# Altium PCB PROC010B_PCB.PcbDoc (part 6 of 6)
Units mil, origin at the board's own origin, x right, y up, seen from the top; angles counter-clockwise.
Board outline 3180 x 2565 mil, 6 copper layers (TOP, L2, L3, L4, L5, BOTTOM), stack 55.54 mil thick; 362 components, 264 nets, 1248 pads, 1144 vias.
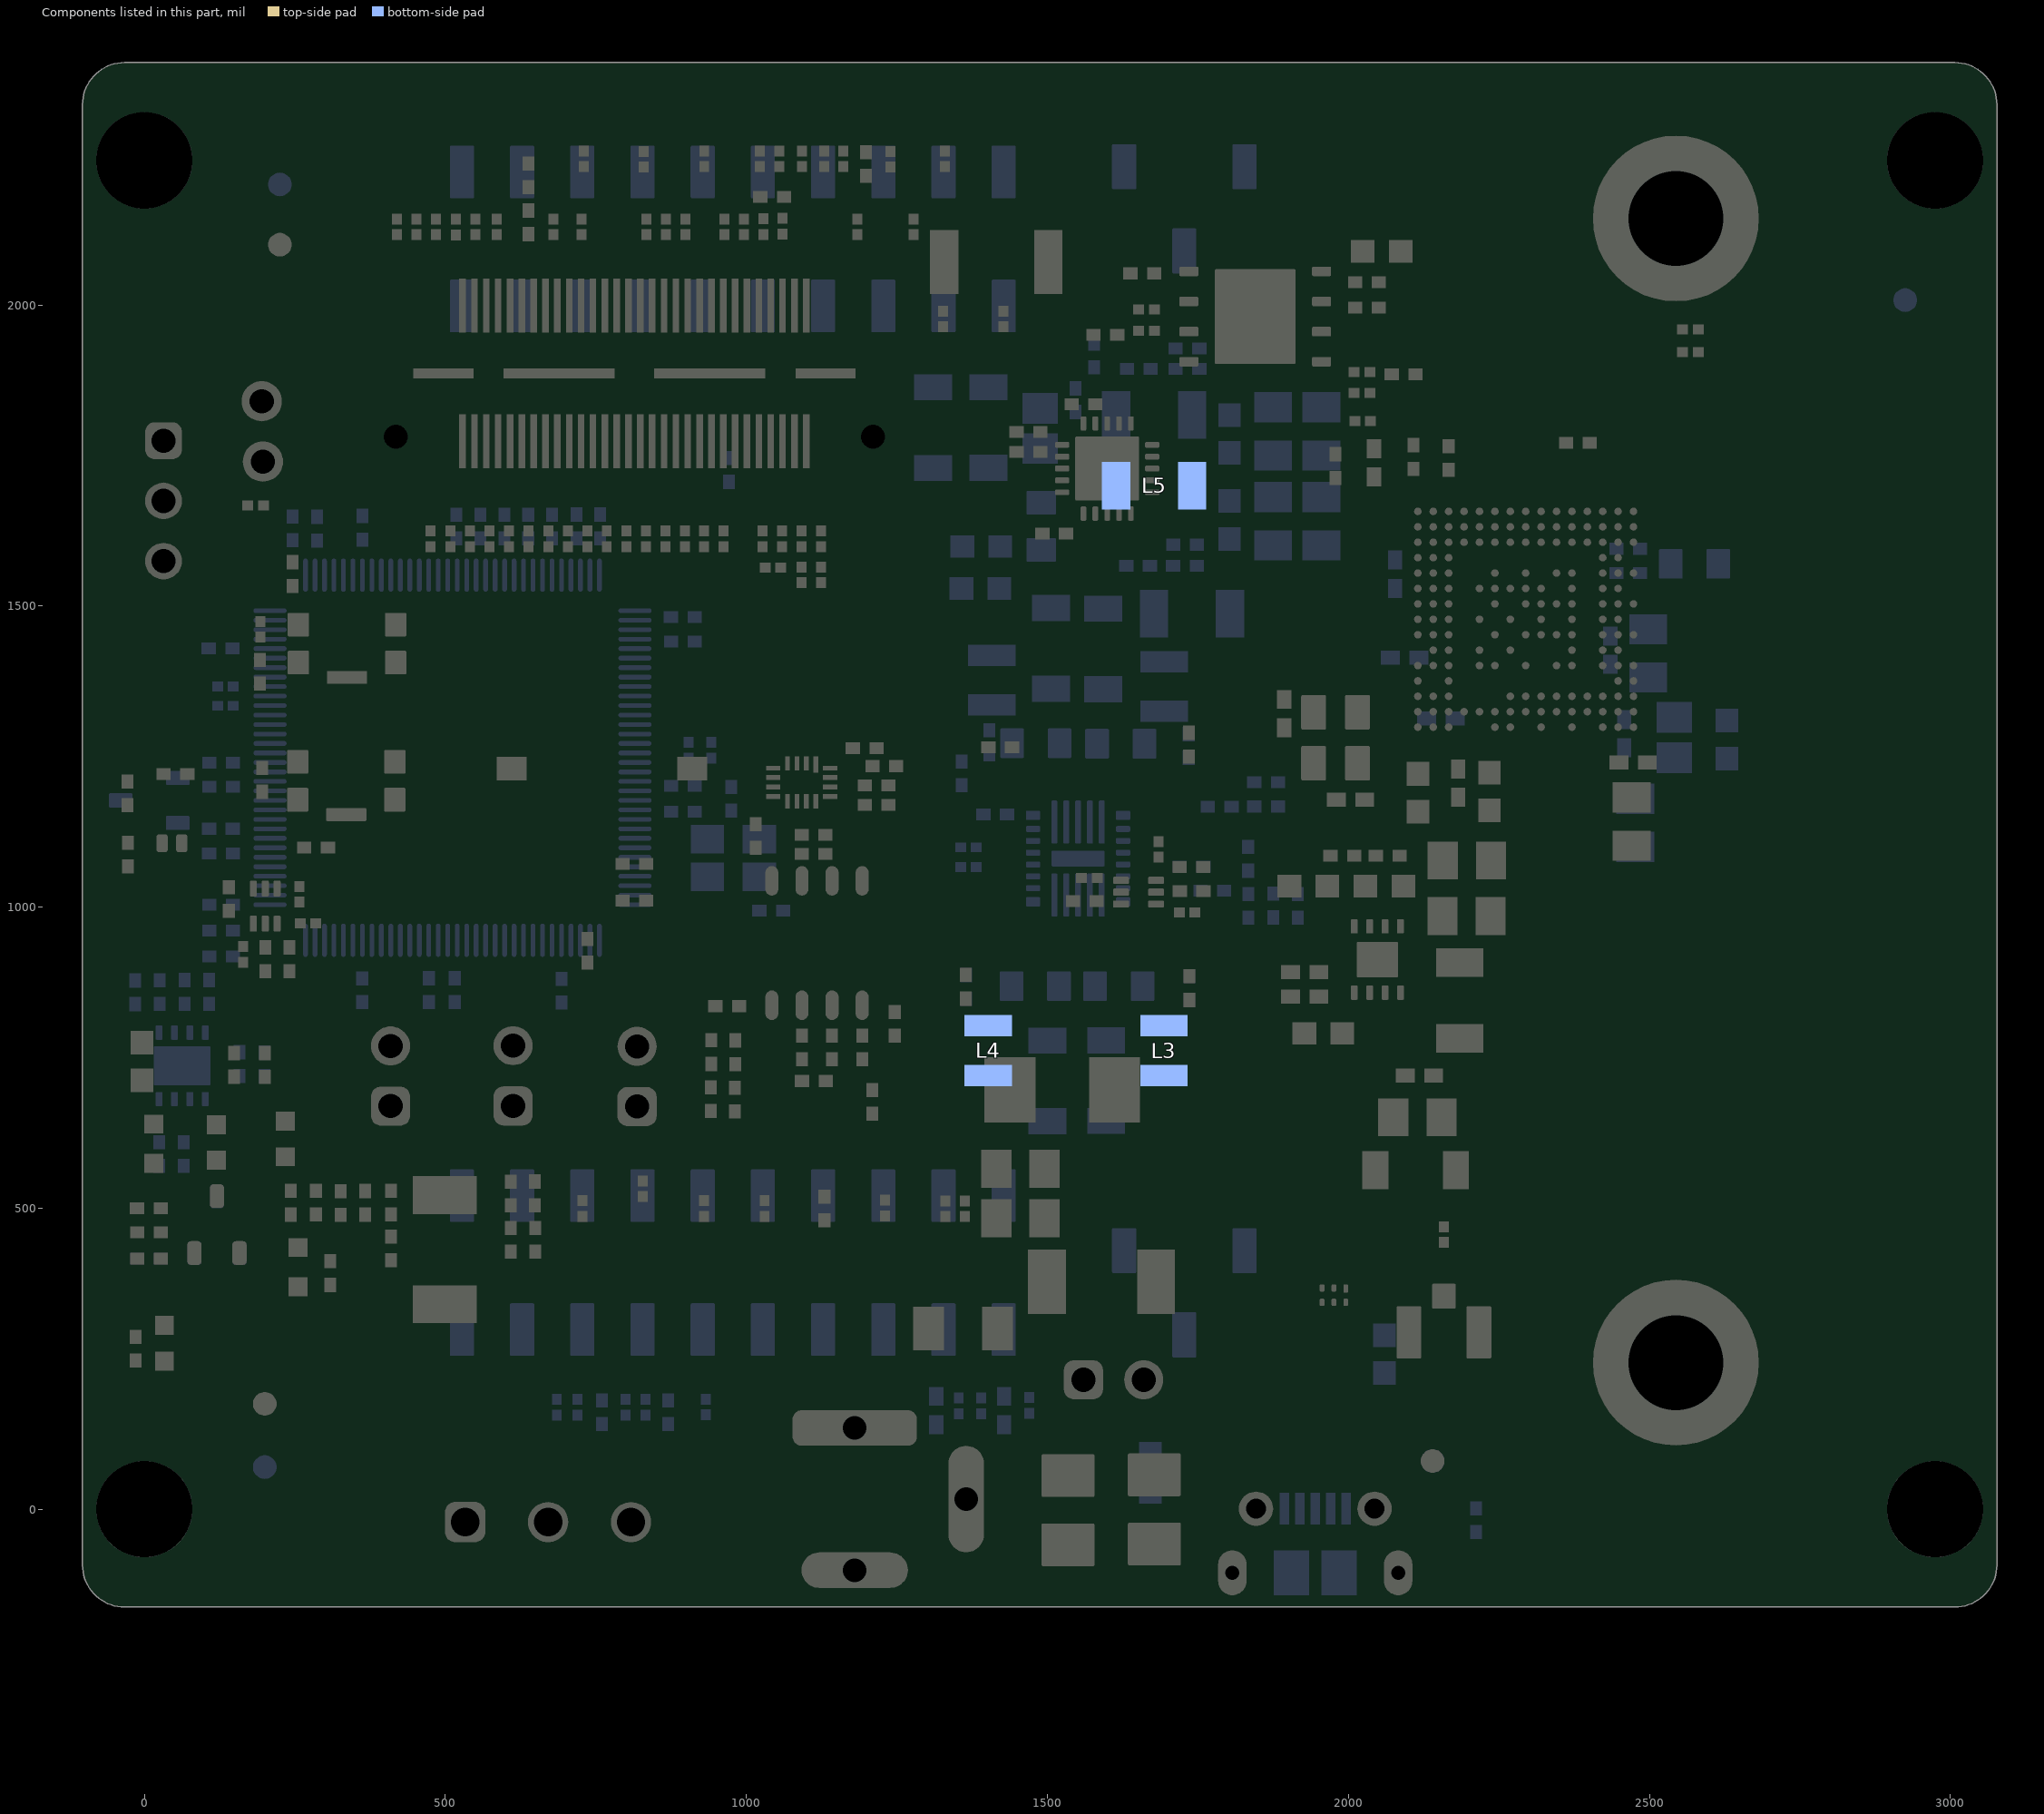
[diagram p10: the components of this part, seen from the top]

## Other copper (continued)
L3:
  pour cut-out: 1600.56,2174.5 1599.22,2181.22 1595.41,2186.91 1589.72,2190.72 1583,2192.06 1576.28,2190.72 1570.59,2186.91 1566.78,2181.22 1565.44,2174.5 1566.78,2167.78 1570.59,2162.09 1576.28,2158.28 1583,2156.94 1589.72,2158.28 1595.41,2162.09 1599.22,2167.78 1600.56,2174.5
  pour cut-out: 1386.56,2172.5 1385.22,2179.22 1381.41,2184.91 1375.72,2188.72 1369,2190.06 1362.28,2188.72 1356.59,2184.91 1352.78,2179.22 1351.44,2172.5 1352.78,2165.78 1356.59,2160.09 1362.28,2156.28 1369,2154.94 1375.72,2156.28 1381.41,2160.09 1385.22,2165.78 1386.56,2172.5
  pour cut-out: 1465.06,1124 1463.72,1130.72 1459.91,1136.41 1454.22,1140.22 1447.5,1141.56 1440.78,1140.22 1435.09,1136.41 1431.28,1130.72 1429.94,1124 1431.28,1117.28 1435.09,1111.59 1440.78,1107.78 1447.5,1106.44 1454.22,1107.78 1459.91,1111.59 1463.72,1117.28 1465.06,1124
  pour cut-out: 1820.56,1102 1819.22,1108.72 1815.41,1114.41 1809.72,1118.22 1803,1119.56 1796.28,1118.22 1790.59,1114.41 1786.78,1108.72 1785.44,1102 1786.78,1095.28 1790.59,1089.59 1796.28,1085.78 1803,1084.44 1809.72,1085.78 1815.41,1089.59 1819.22,1095.28 1820.56,1102
  pour cut-out: 2416.22,1501.7 2414.72,1509.2 2410.48,1515.56 2404.12,1519.8 2396.62,1521.3 2389.12,1519.8 2382.76,1515.56 2378.52,1509.2 2377.02,1501.7 2378.52,1494.2 2382.76,1487.84 2389.12,1483.6 2396.62,1482.1 2404.12,1483.6 2410.48,1487.84 2414.72,1494.2 2416.22,1501.7
  pour cut-out: 2135.56,970.5 2134.22,977.22 2130.41,982.91 2124.72,986.72 2118,988.06 2111.28,986.72 2105.59,982.91 2101.78,977.22 2100.44,970.5 2101.78,963.78 2105.59,958.09 2111.28,954.28 2118,952.94 2124.72,954.28 2130.41,958.09 2134.22,963.78 2135.56,970.5
  pour cut-out: 1881.56,952.5 1880.22,959.22 1876.41,964.91 1870.72,968.72 1864,970.06 1857.28,968.72 1851.59,964.91 1847.78,959.22 1846.44,952.5 1847.78,945.78 1851.59,940.09 1857.28,936.28 1864,934.94 1870.72,936.28 1876.41,940.09 1880.22,945.78 1881.56,952.5
  pour cut-out: 1904.56,1133.5 1903.22,1140.22 1899.41,1145.91 1893.72,1149.72 1887,1151.06 1880.28,1149.72 1874.59,1145.91 1870.78,1140.22 1869.44,1133.5 1870.78,1126.78 1874.59,1121.09 1880.28,1117.28 1887,1115.94 1893.72,1117.28 1899.41,1121.09 1903.22,1126.78 1904.56,1133.5
  pour cut-out: 1933.56,949.5 1932.22,956.22 1928.41,961.91 1922.72,965.72 1916,967.06 1909.28,965.72 1903.59,961.91 1899.78,956.22 1898.44,949.5 1899.78,942.78 1903.59,937.09 1909.28,933.28 1916,931.94 1922.72,933.28 1928.41,937.09 1932.22,942.78 1933.56,949.5
  pour cut-out: 1832.56,689.5 1831.22,696.22 1827.41,701.91 1821.72,705.72 1815,707.06 1808.28,705.72 1802.59,701.91 1798.78,696.22 1797.44,689.5 1798.78,682.78 1802.59,677.09 1808.28,673.28 1815,671.94 1821.72,673.28 1827.41,677.09 1831.22,682.78 1832.56,689.5
  pour cut-out: 1933.56,145.5 1932.22,152.22 1928.41,157.91 1922.72,161.72 1916,163.06 1909.28,161.72 1903.59,157.91 1899.78,152.22 1898.44,145.5 1899.78,138.78 1903.59,133.09 1909.28,129.28 1916,127.94 1922.72,129.28 1928.41,133.09 1932.22,138.78 1933.56,145.5
  pour cut-out: 1041.56,1842.5 1040.22,1849.22 1036.41,1854.91 1030.72,1858.72 1024,1860.06 1017.28,1858.72 1011.59,1854.91 1007.78,1849.22 1006.44,1842.5 1007.78,1835.78 1011.59,1830.09 1017.28,1826.28 1024,1824.94 1030.72,1826.28 1036.41,1830.09 1040.22,1835.78 1041.56,1842.5
  pour cut-out: 807.56,2308.5 806.22,2315.22 802.41,2320.91 796.72,2324.72 790,2326.06 783.28,2324.72 777.59,2320.91 773.78,2315.22 772.44,2308.5 773.78,2301.78 777.59,2296.09 783.28,2292.28 790,2290.94 796.72,2292.28 802.41,2296.09 806.22,2301.78 807.56,2308.5
  pour cut-out: 681.56,850 680.22,856.72 676.41,862.41 670.72,866.22 664,867.56 657.28,866.22 651.59,862.41 647.78,856.72 646.44,850 647.78,843.28 651.59,837.59 657.28,833.78 664,832.44 670.72,833.78 676.41,837.59 680.22,843.28 681.56,850
  pour cut-out: 741.56,125.5 740.22,132.22 736.41,137.91 730.72,141.72 724,143.06 717.28,141.72 711.59,137.91 707.78,132.22 706.44,125.5 707.78,118.78 711.59,113.09 717.28,109.28 724,107.94 730.72,109.28 736.41,113.09 740.22,118.78 741.56,125.5
  pour cut-out: 825.56,128.5 824.22,135.22 820.41,140.91 814.72,144.72 808,146.06 801.28,144.72 795.59,140.91 791.78,135.22 790.44,128.5 791.78,121.78 795.59,116.09 801.28,112.28 808,110.94 814.72,112.28 820.41,116.09 824.22,121.78 825.56,128.5
  pour cut-out: 467.56,2168.5 466.22,2175.22 462.41,2180.91 456.72,2184.72 450,2186.06 443.28,2184.72 437.59,2180.91 433.78,2175.22 432.44,2168.5 433.78,2161.78 437.59,2156.09 443.28,2152.28 450,2150.94 456.72,2152.28 462.41,2156.09 466.22,2161.78 467.56,2168.5
  pour cut-out: 479.56,1272.5 478.22,1279.22 474.41,1284.91 468.72,1288.72 462,1290.06 455.28,1288.72 449.59,1284.91 445.78,1279.22 444.44,1272.5 445.78,1265.78 449.59,1260.09 455.28,1256.28 462,1254.94 468.72,1256.28 474.41,1260.09 478.22,1265.78 479.56,1272.5
  pour cut-out: 468.56,280.5 467.22,287.22 463.41,292.91 457.72,296.72 451,298.06 444.28,296.72 438.59,292.91 434.78,287.22 433.44,280.5 434.78,273.78 438.59,268.09 444.28,264.28 451,262.94 457.72,264.28 463.41,268.09 467.22,273.78 468.56,280.5
  pour cut-out: 579.56,219.5 578.22,226.22 574.41,231.91 568.72,235.72 562,237.06 555.28,235.72 549.59,231.91 545.78,226.22 544.44,219.5 545.78,212.78 549.59,207.09 555.28,203.28 562,201.94 568.72,203.28 574.41,207.09 578.22,212.78 579.56,219.5
  pour cut-out: 527.56,221.5 526.22,228.22 522.41,233.91 516.72,237.72 510,239.06 503.28,237.72 497.59,233.91 493.78,228.22 492.44,221.5 493.78,214.78 497.59,209.09 503.28,205.28 510,203.94 516.72,205.28 522.41,209.09 526.22,214.78 527.56,221.5
  pour cut-out: 491.56,241.5 490.22,248.22 486.41,253.91 480.72,257.72 474,259.06 467.28,257.72 461.59,253.91 457.78,248.22 456.44,241.5 457.78,234.78 461.59,229.09 467.28,225.28 474,223.94 480.72,225.28 486.41,229.09 490.22,234.78 491.56,241.5
  pour cut-out: 366.56,1818.5 365.22,1825.22 361.41,1830.91 355.72,1834.72 349,1836.06 342.28,1834.72 336.59,1830.91 332.78,1825.22 331.44,1818.5 332.78,1811.78 336.59,1806.09 342.28,1802.28 349,1800.94 355.72,1802.28 361.41,1806.09 365.22,1811.78 366.56,1818.5
  pour cut-out: 332.56,1776.5 331.22,1783.22 327.41,1788.91 321.72,1792.72 315,1794.06 308.28,1792.72 302.59,1788.91 298.78,1783.22 297.44,1776.5 298.78,1769.78 302.59,1764.09 308.28,1760.28 315,1758.94 321.72,1760.28 327.41,1764.09 331.22,1769.78 332.56,1776.5
  pour cut-out: 284.56,1680.5 283.22,1687.22 279.41,1692.91 273.72,1696.72 267,1698.06 260.28,1696.72 254.59,1692.91 250.78,1687.22 249.44,1680.5 250.78,1673.78 254.59,1668.09 260.28,1664.28 267,1662.94 273.72,1664.28 279.41,1668.09 283.22,1673.78 284.56,1680.5
  pour cut-out: 142.56,686.5 141.22,693.22 137.41,698.91 131.72,702.72 125,704.06 118.28,702.72 112.59,698.91 108.78,693.22 107.44,686.5 108.78,679.78 112.59,674.09 118.28,670.28 125,668.94 131.72,670.28 137.41,674.09 141.22,679.78 142.56,686.5
  pour cut-out: 231.56,489.5 230.22,496.22 226.41,501.91 220.72,505.72 214,507.06 207.28,505.72 201.59,501.91 197.78,496.22 196.44,489.5 197.78,482.78 201.59,477.09 207.28,473.28 214,471.94 220.72,473.28 226.41,477.09 230.22,482.78 231.56,489.5
  pour cut-out: 334.56,451.5 333.22,458.22 329.41,463.91 323.72,467.72 317,469.06 310.28,467.72 304.59,463.91 300.78,458.22 299.44,451.5 300.78,444.78 304.59,439.09 310.28,435.28 317,433.94 323.72,435.28 329.41,439.09 333.22,444.78 334.56,451.5
  pour cut-out: 72.56,973.5 71.22,980.22 67.41,985.91 61.72,989.72 55,991.06 48.28,989.72 42.59,985.91 38.78,980.22 37.44,973.5 38.78,966.78 42.59,961.09 48.28,957.28 55,955.94 61.72,957.28 67.41,961.09 71.22,966.78 72.56,973.5
  pour cut-out: -14.44,807.5 -15.78,814.22 -19.59,819.91 -25.28,823.72 -32,825.06 -38.72,823.72 -44.41,819.91 -48.22,814.22 -49.56,807.5 -48.22,800.78 -44.41,795.09 -38.72,791.28 -32,789.94 -25.28,791.28 -19.59,795.09 -15.78,800.78 -14.44,807.5
  pour cut-out: 80.56,906.5 79.22,913.22 75.41,918.91 69.72,922.72 63,924.06 56.28,922.72 50.59,918.91 46.78,913.22 45.44,906.5 46.78,899.78 50.59,894.09 56.28,890.28 63,888.94 69.72,890.28 75.41,894.09 79.22,899.78 80.56,906.5
  pour cut-out: -30.44,715.5 -31.78,722.22 -35.59,727.91 -41.28,731.72 -48,733.06 -54.72,731.72 -60.41,727.91 -64.22,722.22 -65.56,715.5 -64.22,708.78 -60.41,703.09 -54.72,699.28 -48,697.94 -41.28,699.28 -35.59,703.09 -31.78,708.78 -30.44,715.5
  pour cut-out: 6.44,373.5 5.1,380.22 1.3,385.91 -4.4,389.72 -11.12,391.06 -17.84,389.72 -23.54,385.91 -27.34,380.22 -28.68,373.5 -27.34,366.78 -23.54,361.09 -17.84,357.28 -11.12,355.94 -4.4,357.28 1.3,361.09 5.1,366.78 6.44,373.5
  pour cut-out: 6.23,531.5 4.89,538.22 1.09,543.91 -4.61,547.72 -11.33,549.06 -18.05,547.72 -23.74,543.91 -27.55,538.22 -28.89,531.5 -27.55,524.78 -23.74,519.09 -18.05,515.28 -11.33,513.94 -4.61,515.28 1.09,519.09 4.89,524.78 6.23,531.5
  pour cut-out: 1425.56,1065 1424.22,1071.72 1420.41,1077.41 1414.72,1081.22 1408,1082.56 1401.28,1081.22 1395.59,1077.41 1391.78,1071.72 1390.44,1065 1391.78,1058.28 1395.59,1052.59 1401.28,1048.78 1408,1047.44 1414.72,1048.78 1420.41,1052.59 1424.22,1058.28 1425.56,1065
  pour cut-out: 1380.56,918 1379.22,924.72 1375.41,930.41 1369.72,934.22 1363,935.56 1356.28,934.22 1350.59,930.41 1346.78,924.72 1345.44,918 1346.78,911.28 1350.59,905.59 1356.28,901.78 1363,900.44 1369.72,901.78 1375.41,905.59 1379.22,911.28 1380.56,918
  pour cut-out: 1161.56,2065.5 1160.22,2072.22 1156.41,2077.91 1150.72,2081.72 1144,2083.06 1137.28,2081.72 1131.59,2077.91 1127.78,2072.22 1126.44,2065.5 1127.78,2058.78 1131.59,2053.09 1137.28,2049.28 1144,2047.94 1150.72,2049.28 1156.41,2053.09 1160.22,2058.78 1161.56,2065.5
  pour cut-out: 1225.56,2281.5 1224.22,2288.22 1220.41,2293.91 1214.72,2297.72 1208,2299.06 1201.28,2297.72 1195.59,2293.91 1191.78,2288.22 1190.44,2281.5 1191.78,2274.78 1195.59,2269.09 1201.28,2265.28 1208,2263.94 1214.72,2265.28 1220.41,2269.09 1224.22,2274.78 1225.56,2281.5
  pour cut-out: 596.76,532.5 595.42,539.22 591.61,544.91 585.92,548.72 579.2,550.06 572.48,548.72 566.78,544.91 562.98,539.22 561.64,532.5 562.98,525.78 566.78,520.09 572.48,516.28 579.2,514.94 585.92,516.28 591.61,520.09 595.42,525.78 596.76,532.5
  pour cut-out: 1589.58,2229.48 1588.24,2236.2 1584.43,2241.9 1578.74,2245.7 1572.02,2247.04 1565.3,2245.7 1559.61,2241.9 1555.8,2236.2 1554.46,2229.48 1555.8,2222.76 1559.61,2217.06 1565.3,2213.26 1572.02,2211.92 1578.74,2213.26 1584.43,2217.06 1588.24,2222.76 1589.58,2229.48
  pour cut-out: 1604.43,2016.01 1603.09,2022.73 1599.28,2028.42 1593.59,2032.23 1586.87,2033.57 1580.15,2032.23 1574.45,2028.42 1570.65,2022.73 1569.31,2016.01 1570.65,2009.29 1574.45,2003.59 1580.15,1999.79 1586.87,1998.45 1593.59,1999.79 1599.28,2003.59 1603.09,2009.29 1604.43,2016.01
  pour cut-out: 2001.15,1420.93 2001.15,1399.1 2010.71,1389.54 2033.02,1389.54 2042.9,1399.42 2042.9,1422.35 2034.76,1430.49 2010.7,1430.49
  pour cut-out: 2388.47,801.94 2388.47,787.64 2399.47,776.64 2411.42,776.64 2420.44,785.66 2420.44,800.04 2411.42,809.06 2395.59,809.06
  pour cut-out: 2325.12,882.28 2325.12,867.98 2336.12,856.98 2348.06,856.98 2357.09,866 2357.09,880.38 2348.06,889.4 2332.24,889.4
  pour cut-out: 2072.08,1321.15 2072.08,1305.01 2081.98,1295.11 2101.41,1295.11 2114.7,1308.4 2114.7,1320.49 2104.79,1330.41 2081.34,1330.41
  pour cut-out: 1755.04,2103.69 1755.04,2078.14 1763.26,2069.92 1780.02,2069.92 1796.11,2086.02 1796.11,2105.18 1789.22,2112.08 1763.42,2112.08
  pour cut-out: 2060.04,2009.43 2060.04,1983.88 2068.26,1975.66 2085.02,1975.66 2101.11,1991.76 2101.11,2010.92 2094.22,2017.82 2068.42,2017.82
  pour cut-out: 2221.47,724.94 2221.47,706.23 2231.08,696.62 2245.63,696.62 2253.44,704.43 2253.44,724.46 2245.84,732.06 2228.59,732.06
  pour cut-out: 216.76,785.5 215.42,792.22 211.62,797.91 205.92,801.72 199.2,803.06 192.48,801.72 186.79,797.91 182.98,792.22 181.64,785.5 182.98,778.78 186.79,773.09 192.48,769.28 199.2,767.94 205.92,769.28 211.62,773.09 215.42,778.78 216.76,785.5
  pour cut-out: 1078.54,924.46 1077.21,931.18 1073.4,936.88 1067.7,940.68 1060.98,942.02 1054.27,940.68 1048.57,936.88 1044.76,931.18 1043.43,924.46 1044.76,917.74 1048.57,912.05 1054.27,908.24 1060.98,906.9 1067.7,908.24 1073.4,912.05 1077.21,917.74 1078.54,924.46
  pour cut-out: 2470.18,1676.36 2470.18,1662.36 2496.03,1636.52 2510.94,1636.52 2510.94,1707.84 2501.66,1707.84
  pour cut-out: 930.41,1685.77 930.41,1690.52 920.25,1700.69 920.25,1723.05 929.65,1732.45 971.87,1732.45 974.54,1729.79
  pour cut-out: 2186.37,1031.38 2185.03,1038.1 2181.23,1043.8 2175.53,1047.6 2168.81,1048.94 2162.09,1047.6 2156.4,1043.8 2152.59,1038.1 2151.26,1031.38 2152.59,1024.67 2156.4,1018.97 2162.09,1015.16 2168.81,1013.83 2175.53,1015.16 2181.23,1018.97 2185.03,1024.67 2186.37,1031.38
  pour cut-out: 2269.24,957 2269.24,942.7 2280.24,931.7 2292.18,931.7 2301.2,940.73 2301.2,955.1 2292.18,964.12 2276.36,964.12
  text "3" at 68.06,102.36 h50
  text ".Layer_Name" at -523,-1458.49 h60
L4:
  drawing of 93 lines, arcs and shapes, not listed
  text "4" at 68.06,102.36 h50
  text ".Layer_Name" at -523,-1458.49 h60
L5:
  text "5" at 68.06,102.36 h50
  text ".Layer_Name" at -523,-1458.49 h60
BOTTOM:
  pour cut-out: 2691.21,2143.55 2689.4,2166.59 2684.01,2189.06 2675.16,2210.41 2663.09,2230.11 2648.08,2247.68 2630.51,2262.69 2610.81,2274.76 2589.46,2283.61 2566.99,2289 2543.95,2290.81 2520.91,2289 2498.44,2283.61 2477.09,2274.76 2457.39,2262.69 2439.82,2247.68 2424.81,2230.11 2412.74,2210.41 2403.89,2189.06 2398.5,2166.59 2396.69,2143.55 2398.5,2120.51 2403.89,2098.04 2412.74,2076.69 2424.81,2056.99 2439.82,2039.42 2457.39,2024.41 2477.09,2012.34 2498.44,2003.49 2520.91,1998.1 2543.95,1996.29 2566.99,1998.1 2589.46,2003.49 2610.81,2012.34 2630.51,2024.41 2648.08,2039.42 2663.09,2056.99 2675.16,2076.69 2684.01,2098.04 2689.4,2120.51 2691.21,2143.55
  pour cut-out: 2691.21,243.55 2689.4,266.59 2684.01,289.06 2675.16,310.41 2663.09,330.11 2648.08,347.68 2630.51,362.69 2610.81,374.76 2589.46,383.61 2566.99,389 2543.95,390.81 2520.91,389 2498.44,383.61 2477.09,374.76 2457.39,362.69 2439.82,347.68 2424.81,330.11 2412.74,310.41 2403.89,289.06 2398.5,266.59 2396.69,243.55 2398.5,220.51 2403.89,198.04 2412.74,176.69 2424.81,156.99 2439.82,139.42 2457.39,124.41 2477.09,112.34 2498.44,103.49 2520.91,98.1 2543.95,96.29 2566.99,98.1 2589.46,103.49 2610.81,112.34 2630.51,124.41 2648.08,139.42 2663.09,156.99 2675.16,176.69 2684.01,198.04 2689.4,220.51 2691.21,243.55
  pour cut-out: 2027.6,469.16 2026.1,476.66 2021.86,483.02 2015.5,487.26 2008,488.76 2000.5,487.26 1994.14,483.02 1989.9,476.66 1988.4,469.16 1989.9,461.66 1994.14,455.3 2000.5,451.06 2008,449.56 2015.5,451.06 2021.86,455.3 2026.1,461.66 2027.6,469.16
  pour cut-out: 2559.6,1753.5 2558.1,1761 2553.86,1767.36 2547.5,1771.6 2540,1773.1 2532.5,1771.6 2526.14,1767.36 2521.9,1761 2520.4,1753.5 2521.9,1746 2526.14,1739.64 2532.5,1735.4 2540,1733.9 2547.5,1735.4 2553.86,1739.64 2558.1,1746 2559.6,1753.5
  pour cut-out: 2597.6,1841.5 2596.1,1849 2591.86,1855.36 2585.5,1859.6 2578,1861.1 2570.5,1859.6 2564.14,1855.36 2559.9,1849 2558.4,1841.5 2559.9,1834 2564.14,1827.64 2570.5,1823.4 2578,1821.9 2585.5,1823.4 2591.86,1827.64 2596.1,1834 2597.6,1841.5
  pour cut-out: 2920.17,1934.93 2918.67,1942.43 2914.43,1948.79 2908.07,1953.03 2900.57,1954.53 2893.07,1953.03 2886.71,1948.79 2882.47,1942.43 2880.97,1934.93 2882.47,1927.43 2886.71,1921.07 2893.07,1916.83 2900.57,1915.33 2908.07,1916.83 2914.43,1921.07 2918.67,1927.43 2920.17,1934.93
  pour cut-out: 2863.6,1991.5 2862.1,1999 2857.86,2005.36 2851.5,2009.6 2844,2011.1 2836.5,2009.6 2830.14,2005.36 2825.9,1999 2824.4,1991.5 2825.9,1984 2830.14,1977.64 2836.5,1973.4 2844,1971.9 2851.5,1973.4 2857.86,1977.64 2862.1,1984 2863.6,1991.5
  pour cut-out: 2151.7,1291.49 2147.75,1291.49 2115.09,1258.83 2115.09,1267.92 2129.83,1282.66 2129.83,1293.11 2123.32,1299.62 2097.57,1299.62 2093.78,1295.83 2084.86,1295.83 2077.28,1303.41 2077.28,1358.83 2083.95,1365.49 2097.57,1365.49 2103.93,1359.14 2103.93,1333.24 2107.42,1329.76 2150.88,1329.76 2156.72,1323.91 2156.72,1296.51
  pour cut-out: 2115.09,1148.14 2115.09,1128.65 2129.49,1114.24 2123.74,1108.49 2093.29,1108.49 2085.17,1116.61 2085.17,1128.76 2096.68,1140.27 2107.22,1140.27
  text "6" at 101.39,102.36 h50
  text ".Layer_Name" at -523,-1458.49 h60

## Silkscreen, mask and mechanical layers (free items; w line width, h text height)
Top Overlay:
  circle w6: c894.62,627.38 r17.83
  circle w6: c485.18,628.05 r17.83
  circle w6: c688.62,628.38 r17.83
  circle w6: c-42.06,1837.57 r14.11
  circle w6: c1489.33,267.42 r14.11
  circle w6: c2007.63,386.64 r7.14
  text "HD_CONN" at 325,1793.5 h35 r90
  text "GND" at -48.33,1613 h35 r90
  text "1243/1443-EVM" at 648,1502.5 h30
  text "PROC010 REV B" at 652,1437.33 h30
  text "GPIO1" at 504.55,1382.74 h35 r90
  text "SPI" at 569.09,1196.05 h35 r90
  text "CAN" at 987.03,1180.35 h35 r90
  text "NRST" at 504.55,1144.97 h35 r90
  text "ON" at 914.7,1109.62 h35 r90.31
  text "SOP2" at 424,836.5 h35 r90
  text "SOP1" at 624,831.5 h35 r90
  text "SOP0" at 829,831.5 h35 r90
  text "5V" at 278.28,691.14 h35 r90
  text "NERR_OUT" at 107.44,686.5 h35 r90
  text "5V_IN" at 1117.5,271 h35
  text "NRST" at 298.71,228.51 h35 r90
  text "WARMRST" at 134.9,184 h32 r89.47
  text "GND" at 679.67,133 h35 r90
  text "CAN_L" at 963.67,65 h35 r90
  text "CAN_H" at 439.67,64 h35 r90
  text "USB" at 1958,-52.5 h35 r90
  text ".Layer_Name" at -523,-1458.49 h60
Bottom Overlay:
  drawing of 8192 lines, arcs and shapes, not listed
  text "GND" at 1635.34,2394.5 h35 r90
  text "GND" at 1736.34,2394.5 h35 r90
  text "GND" at 544.67,2389.5 h35 r90
  text "3V3" at 1842.66,2383.93 h30 r90
  text "GND" at 691.34,695.5 h35 r90
  text "GND" at 1639.34,609.5 h35 r90
  text "GND" at 1748.34,608.5 h35 r90
  text ".Layer_Name" at -523,-1458.49 h60
Top Paste:
  text ".Layer_Name" at -523,-1458.49 h60
Bottom Paste:
  text ".Layer_Name" at -523,-1458.49 h60
Top Solder:
  text ".Layer_Name" at -523,-1458.49 h60
  text ".Layer_Name" at -523,-1458.49 h60
Bottom Solder:
  pour cut-out: 1481.31,1176.95 1481.31,1160.02 1464.38,1160.02 1464.38,1144.28 1495.09,1144.28 1495.09,1176.95 1481.31,1176.95
  pour cut-out: 1620.69,1176.95 1620.69,1160.02 1637.62,1160.02 1637.62,1144.28 1606.91,1144.28 1606.91,1176.95 1620.69,1176.95
  pour cut-out: 1481.31,984.05 1481.31,1000.98 1464.38,1000.98 1464.38,1016.72 1495.09,1016.72 1495.09,984.05 1481.31,984.05
  pour cut-out: 1620.69,984.05 1620.69,1000.98 1637.62,1000.98 1637.62,1016.72 1606.91,1016.72 1606.91,984.05 1620.69,984.05
  text ".Layer_Name" at -523,-1458.49 h60
Drill Guide:
  text ".Layer_Name" at -523,-1458.49 h60
M1 Board Outline:
  the board outline again, w10
M3 3D STEP Top:
  drawing of 2189 lines, arcs and shapes, not listed
  text ".Layer_Name" at -523,-1458.49 h60
M4 3D STEP Bottom:
  drawing of 3548 lines, arcs and shapes, not listed
  text ".Layer_Name" at -523,-1458.49 h60
M5 Assembly Top:
  region: 1573.73,232.01 1541.58,232.01 1541.58,199 1573.73,199
  rectangle: 3.25,1755.12 61.5,1795.24
  rectangle: 392.36,652.17 425.79,686.46
  rectangle: 595.1,653.88 628.11,683.89
  rectangle: 804.71,651.74 836.86,684.75
  rectangle: 505.35,-45.85 561.85,-0.8
  lines w10: -1392,-1530.17 5208,-1530.17 ; -1392,-1326.83 5210,-1326.83 ; -1392,-1123.5 -1392,-1733.5 2613,-1733.5 5210,-1733.5 5210,-1123.5 -1391.5,-1123.5 -1391.5,-1733.5 184,-1733.5 ; 1073,-1733.5 1073,-1123.5 ; 2340,-1326.83 2340,-1123.5 ; 3180,-1326.83 3180,-1123.5 ; 3802,-1740 3802,-1537.17
  text "COMPONENTS MARKED 'DNP' SHOULD NOT BE POPULATED." at 53.5,-918.5 h60
  text "ASSEMBLY VARIANT:" at 53,-1034 h60
  text ".VariantName" at 1089,-1034 h60
  text "PCB VIEWED FROM TOP SIDE" at -1328.5,-1255.67 h60
  text "BOARD #:" at 1148,-1255.67 h60
  text ".PRJ_Number" at 1693.5,-1255.67 h60
  text "REV:" at 2538,-1255.67 h60
  text ".PCB_Rev" at 2829.5,-1255.67 h60
  text "SVN REV:" at 3376,-1255.67 h60
  text ".VersionControl_RevNumber" at 3882,-1255.67 h60
  text "TID #:" at 1148,-1459 h60
  text ".TID" at 1693.5,-1459 h60
  text "PLOT NAME =" at -1328.5,-1664.34 h60
  text ".plot_File_Name" at -523,-1664.34 h60
  text "GENERATED    :" at 1150,-1664.34 h60
  text ".Print_Date" at 2019.5,-1664.34 h60
  text ".Print_Time" at 2748.5,-1664.34 h60
  text "TEXAS INSTRUMENTS" at 4013,-1664.34 h60
M6 Assembly Bottom:
  rectangle: 477.5,309.5 520.87,346.52
  rectangle: 477.5,2009.5 520.08,2041.65
  lines w10: -1392.5,-1327.33 5209.5,-1327.33 ; -1390.5,-1530.67 5209.5,-1530.67 ; 15.5,-1740.5 15.5,-1537.67 ; 637.5,-1327.33 637.5,-1124 ; 1477.5,-1327.33 1477.5,-1124 ; 2744.5,-1734 2744.5,-1124 ; 3633.5,-1734 5209,-1734 5209,-1124 -1392.5,-1124 -1392.5,-1734 1204.5,-1734 5209.5,-1734 5209.5,-1124
  text "COMPONENTS MARKED 'DNP' SHOULD NOT BE POPULATED." at 5002,-918 h60
  text ".VariantName" at 3958,-1034 h60
  text "ASSEMBLY VARIANT:" at 4997,-1034 h60
  text ".VersionControl_RevNumber" at -64.5,-1256.17 h60
  text "SVN REV:" at 441.5,-1256.17 h60
  text ".PCB_Rev" at 988,-1256.17 h60
  text "REV:" at 1279.5,-1256.17 h60
  text ".PRJ_Number" at 2124,-1256.17 h60
  text "BOARD #:" at 2669.5,-1256.17 h60
  text "PCB VIEWED FROM BOTTOM SIDE" at 5146,-1256.17 h60
  text ".TID" at 2124,-1459.5 h60
  text "TID #:" at 2669.5,-1459.5 h60
  text "TEXAS INSTRUMENTS" at -195.5,-1664.84 h60
  text ".Print_Time" at 1069,-1664.84 h60
  text ".Print_Date" at 1798,-1664.84 h60
  text "GENERATED    :" at 2667.5,-1664.84 h60
  text ".plot_File_Name" at 4340.5,-1664.84 h60
  text "PLOT NAME =" at 5146,-1664.84 h60
1:
  lines w1: 2633.36,918.75 2633.36,1666.78 3042.41,1666.78 3042.41,918.75 2633.36,918.75
2:
  drawing of 7 lines, arcs and shapes, not listed
M9 Title Sheet:
  drawing of 59 lines, arcs and shapes, not listed
  text "1" at -360.16,7436.5 h70
  text "2" at 2135.5,7436.5 h70
  text "3" at 4624.84,7436.5 h70
  text "4" at 7131.51,7436.5 h70
  text "5" at 9630.5,7436.5 h70
  text "6" at 12135.5,7436.5 h70
  text "A" at -1516.5,6293.5 h70
  text "A" at 13283.5,6293.5 h70
  text "B" at -1516.5,3913.5 h70
  text "B" at 13283.5,3913.5 h70
  text "C" at -1516.5,1538.5 h70
  text "C" at 13283.5,1538.5 h70
  text "PROJECT TITLE:" at 10243.5,-322.5 h45
  text ".PRJ_Title" at 10293.5,-455.83 h70
  text "DESIGNED FOR:" at 10243.5,-623.5 h45
  text ".PRJ_Customer" at 10293.5,-763.5 h70
  text "D" at -1516.5,-831.5 h70
  text "D" at 13283.5,-831.5 h70
  text "FILE NAME:" at 10243.5,-923.5 h45
  text ".PCB_File_Name_No_Path" at 10293.5,-1043.5 h70
  text "Texas Instruments (TI) and/or its licensors do not warrant the accuracy or completeness of this specification" at 5274,-1205.34 h45
  text "ENGINEER:" at 10243.5,-1213.5 h45
  text "LAYOUT BY:" at 11748.5,-1213.5 h45
  text "or any information contained therein. TI and/or its licensors do not warrant that this design will meet" at 5229.01,-1318 h45
  text ".PRJ_Engineer" at 10293.5,-1368.49 h70
  text ".PCB_Layout" at 11799,-1368.49 h70
  text "the specifications, will be suitable for your application or fit for any particular purpose, or will operate in" at 5229.01,-1430.67 h45
  text "ALTIUM DESIGNER VERSION:" at 11748.5,-1523.5 h45
  text "an implementation. TI and/or its licensors do not warrant that the design is production worthy. You should" at 5229.01,-1543.33 h45
  text "completely validate and test your design implementation to confirm the system functionality for your application." at 5274,-1656 h45
  text ".print_Scale" at 10293.5,-1656.83 h70
  text ".Application_BuildNumber" at 11799,-1656.83 h70
  text "1" at -360.16,-1863.5 h70
  text "2" at 2135.5,-1863.5 h70
  text "3" at 4624.84,-1863.5 h70
  text "4" at 7131.51,-1863.5 h70
  text "5" at 9630.5,-1863.5 h70
  text "WO # : 307314-7312-D" at 12135.5,-1863.5 h70
M10 Fab Notes:
  drawing of 211 lines, arcs and shapes, not listed
  text "DESIGN INFORMATION" at 11282.02,5756.17 h60
  text "3.9" at 11684.18,5628.43 h60
  text "MIN. TRACK WIDTH:" at 10637.46,5624.05 h60
  text "MIL" at 11888.46,5624.05 h60
  text "3.9" at 11684.18,5505.31 h60
  text "MIN. CLEARANCE:" at 10637.46,5499.92 h60
  text "MIL" at 11887.46,5493.05 h60
  text "13.77" at 11607.21,5377.48 h60
  text "MIN. VIA PAD SIZE:" at 10637.46,5375.8 h60
  text "MIL" at 11888.46,5375.8 h60
  text "0.05mm (2MIL)" at 11332.46,5245.9 h60
  text "MINIMUM ANNULAR RING" at 10308.23,5237.67 h60
  text "EXTERNAL" at 12040.46,5237.67 h60
  text "PER" at 10508.23,5127.55 h60
  text "IPC-D-275 CLASS 2 LEVEL C" at 10728.23,5127.54 h60
  text "MIL, HOLES" at 12216.46,5027.07 h60
  text "+/-" at 11824,5018.48 h60
  text "+/-" at 12678,5018.48 h60
  text "REGISTRATION TOLERANCES:" at 10308.23,5017.42 h60
  text "METAL" at 11508,5017.42 h60
  text "2" at 12084.2,5017.42 h60
  text "3" at 12917.2,5017.42 h60
  text "MIL" at 13033.46,5017.42 h60
  text "HOLE SIZE TOLERANCE (UNLESS OTHERWISE SPECIFIED):" at 10308.23,4919.1 h60
  text "+/-" at 12678,4916.23 h60
  text "3" at 12917.2,4915.17 h60
  text "MIL" at 13033.46,4915.17 h60
  text "MATERIAL:" at 10233.46,4777.52 h60
  text "FR-4 High Tg" at 11219.9,4649 h60
  text "REFER STACKUP" at 12479.29,4645.02 h60
  text "X" at 11955.46,4641.01 h60
  text "FR-408" at 10654.46,4636.49 h60
  text "OTHER" at 12142.46,4636.49 h60
  text "X" at 12138.91,4493.91 h60
  text "62 MIL (1.6mm) +/-10%" at 10974.56,4493.46 h60
  text "57.14 MIL +/-10%" at 12537.59,4492.07 h50
  text "THICKNESS:" at 10308.23,4485.24 h60
  text "OTHER" at 12259.46,4485.24 h60
  text "TOLERANCE:" at 10308.23,4346.92 h60
  text "X" at 11156.46,4346.92 h60
  text "ANSI IPC-6012 TYPE 3 CLASS 2" at 11334.48,4346.92 h60
  text "OTHER +/-" at 11334.46,4202.73 h60
  text "BOW & TWIST:" at 10308.23,4057.54 h60
  text "X" at 11156.46,4057.54 h60
  text "ANSI IPC-6012 TYPE 3 CLASS 2" at 11334.48,4057.54 h60
  text "OTHER +/-" at 11334.46,3910.85 h60
  text "DRILLING:" at 10233.46,3780.23 h60
  text "NC_DRILL FILES" at 11994.46,3675.04 h60
  text "REFERENCE:" at 10308.23,3671.1 h60
  text "X" at 10965.46,3671.01 h60
  text "AS SHOWN" at 11143.46,3671.1 h60
  text "X" at 11866.46,3671.1 h60
  text "OTHER" at 12292.46,3528.85 h60
  text "PTH COPPER THICKNESS:" at 10307.91,3525.32 h60
  text "X" at 11447.14,3525.32 h60
  text "20-30 um" at 11575.14,3525.32 h60
  text "BOARD FINISH:" at 10233.46,3377.73 h60
  text "SILKSCREEN:" at 10388.68,3267.6 h60
  text "X" at 11346.46,3267.6 h60
  text "TOP" at 11463.46,3267.6 h60
  text "X" at 11856.46,3267.6 h60
  text "BOTTOM" at 11974.46,3267.6 h60
  text "SILKSCREEN COLOR:" at 10388.68,3112.41 h60
  text "X" at 11345.46,3112.41 h60
  text "WHITE" at 11463.46,3112.41 h60
  text "OTHER" at 11974.46,3112.41 h60
  text "REFER NOTE 8" at 12531.96,2973.55 h60
  text "GREEN" at 11594.46,2968.96 h60
  text "X" at 12068.46,2968.96 h60
  text "OTHER" at 12212.46,2968.96 h60
  text "SOLDER RESIST COLOR:" at 10388.68,2962.1 h60
  text "X" at 11476.46,2814.71 h60
  text "MATTE" at 11594.46,2814.71 h60
  text "SEMI-GLOSS" at 12212,2814.07 h60
  text "IMMERSION GOLD (ENIG)" at 11294.46,2641.94 h60
  text "ENEPIG" at 12632,2634.72 h60
  text "SURFACE FINISH:" at 10233.46,2633.72 h60
  text "REFER NOTE 7" at 12356.19,2502.8 h60
  text "IMM. TIN/SILVER OR EQUIV" at 10563,2496.4 h60
  text "X" at 11822.92,2493.72 h60
  text "OTHER" at 11994.46,2492.47 h60
  text "ARRAY/PANEL:" at 10233.46,2337.09 h60
  text "CUT AND TRIM PER M1 BOARD OUTLINE" at 11294.46,2328.87 h60
  text "NOTES : UNLESS OTHERWISE SPECIFIED." at 4571.25,2263.62 h60
  text "N.C. ROUTE" at 11294.46,2192.9 h60
  text "X" at 11982.46,2192.9 h60
  text "V. SCORE" at 12160.46,2192.9 h60
  text "1. ALL VIAS ARE TENTED ON BOTH SIDES UNLESS SOLDERMASK OPENED IN GERBER." at 4680.97,2112.73 h60
  text "CERTIFICATION:" at 10233.46,2063.77 h60
  text "MATERIALS AND WORKMANSHIP FOR ALL PCBS" at 10958.46,2063.77 h60
  text "2. ALL VIAS ON PAD INCLUDING BGA AREA SHOULD BE FILLED WITH NON CONDUCTIVE EPOXY AND SURFACE SHOULD BE FLAT" at 4668.66,1987.45 h60
  text "TO MEET OR EXCEED THE REQUIREMENTS OF:" at 10958.46,1969.71 h60
  text "THERE ARE MANY VIAS ON THE PCB WHICH ARE EITHER ON THE PADS OR CLOSE TO PADS" at 4787.44,1880.17 h60
  text "X" at 10595.97,1841.08 h60
  text "ANSI IPC-A-600F CLASS ->" at 10723.96,1841.08 h60
  text "X" at 12371.97,1841.08 h60
  text "2" at 12481.96,1841.08 h60
  text "1" at 12166.96,1839.58 h60
  text "3" at 12835.96,1839.58 h60
  text "THESE NEED TO BE FILLED WITH A NON-CONDUCTIVE EPOXY TO ENSURE FLAT SURFACE." at 4787.44,1779.43 h60
  text "X" at 11407.97,1693.39 h60
  text "RoHS" at 11535.96,1693.39 h60
  text "OTHER" at 12180.36,1693.39 h60
  text "PER ORDER" at 12577.42,1693.39 h60
  text "BGA AREA VIAS SHOULD BE CAPPED WITH COPPER PLATING TO ENSURE FLAT SURFACE" at 4792.93,1677.9 h60
  text "FLATNESS TOLERANCE FOR VIA ON PADS: +0.000 /- 0.001 INCHES ON BOTH SIDES." at 4792.93,1569.81 h60
  text "ALL BOARDS MUST MEET OR EXCEED UL94-V0 REQUIREMENTS." at 10261,1539.57 h60
  text "3. MANUFACTURER'S IDENTIFICATION, DATECODE LETTER SHALL BE SILKSCREENED ON SOLDER SIDE OF THE BOARD." at 4669.6,1436.68 h60
  text "PCB MUST BEAR THE UL94V-0 UL REGISTERED MATERIAL ID NUMBER" at 10261,1423.5 h60
  text "4. TRACE WIDTH SHOULD BE ACCURATELY ETCHED. MAX TOLERANCE +/- 1 MIL" at 4669.6,1299.99 h60
  text "ADDITIONAL REQUIREMENTS:" at 10233.46,1254.08 h60
  text "5. FOR IMPEDANCE DETAILS REFER STACKUP & IMPEDANCE TABLE." at 4669.6,1159.9 h60
  text "MICROSECTION:" at 10308.23,1146.95 h60
  text "YES" at 11213.96,1146.95 h60
  text "REQUIRED" at 12075.46,1002.62 h60
  text "BARE BOARD ELEC. TEST:" at 10308.23,999.76 h60
  text "NONE" at 11613.96,999.76 h60
  text "X" at 11957.46,999.76 h60
  text "PER ORDER" at 12667.46,999.76 h60
  text "6. SOLDER MASK OPENING IS KEPT SAME SIZE AS PAD (1:1) FOR ALL COMPONENTS EXCEPT U2" at 4669.6,995.9 h60
  text "THE MANUFACTURER IS REQUESTED TO SIZE IT AS PER THEIR SOLDERMASK TOLERANCE." at 4784.01,889.17 h60
  text "XX MIL VIAS REQUIRE NON-CONDUCTIVE FILL AND PLANARIZE" at 10476.38,794.82 h59
  text "FOR U2 (BGA) PLEASE FOLLOW SAME SOLDERMASK SIZE AS GERBER" at 4796.11,779.23 h60
  text "XX MIL VIAS REQUIRE CONDUCTIVE FILL AND PLANARIZE" at 10484.38,690.84 h60
  text "7. SURFACE FINISH: IMMERSION SILVER" at 4669.6,641.3 h60
  text "OUTER XX MIL TRACES REQUIRE 50 OHM SINGLE-ENDED IMPEDANCE" at 10483.39,527.46 h56
  text "8. SOLDERMASK ON BOTH SIDES OF THE BOARD SHALL BE LPI, COLOR RED." at 4669.6,467.34 h60
  text "LAYER 2 & 3 (INNER LAYERS) XX MIL WIDE, XX MIL SPACE / TRACES REQUIRE 100 OHM DIFFERENTIAL IMPEDANCE" at 10475.39,291.74 h60
  text "9. FOR ANTENNA ETCHING TOLERANCE REFER \"ANTENNA ETCHING REQUIREMETS\" DOCUMENT." at 4669.6,288.48 h60
  text "10. THE FOUR GND NET ANTENNAS NEAR Y1 ARE INTENTIONAL" at 4634.42,154.85 h60
M11 Gerber Information:
  lines w10: -1392,-1530.17 5208,-1530.17 ; -1392,-1326.83 5210,-1326.83 ; -1392,-1123.5 -1392,-1733.5 2613,-1733.5 5210,-1733.5 5210,-1123.5 -1391.5,-1123.5 -1391.5,-1733.5 184,-1733.5 ; 1073,-1733.5 1073,-1123.5 ; 2340,-1326.83 2340,-1123.5 ; 3180,-1326.83 3180,-1123.5 ; 3802,-1740 3802,-1537.17
  text "ALL ARTWORK VIEWED FROM TOP SIDE" at -1328.5,-1255.67 h60
  text "BOARD #:" at 1148,-1255.67 h60
  text ".PRJ_Number" at 1693.5,-1255.67 h60
  text "REV:" at 2538,-1255.67 h60
  text ".PCB_Rev" at 2829.5,-1255.67 h60
  text "SVN REV:" at 3376,-1255.67 h60
  text ".VersionControl_RevNumber" at 3882,-1255.67 h60
  text "LAYER NAME =" at -1328.5,-1458.49 h60
  text "TID #:" at 1148,-1459 h60
  text ".TID" at 1693.5,-1459 h60
  text "GENERATED    :" at 1150,-1664.34 h60
  text ".Print_Date" at 2019.5,-1664.34 h60
  text ".Print_Time" at 2748.5,-1664.34 h60
  text "TEXAS INSTRUMENTS" at 4013,-1664.34 h60
M12 Stackup:
  drawing of 480 lines, arcs and shapes, not listed
  text "LAYER STACKUP :" at -787.01,7220.54 h60
  text "Layer" at -787.72,7069.91 h50
  text "Name" at -444.79,7069.91 h50
  text "Material" at 331.33,7069.91 h50
  text "Thickness" at 1049.14,7069.91 h50
  text "Constant" at 1592,7069.91 h50
  text "Board Layer Stack" at 2068.22,7069.91 h50
  text "1" at -787.72,6969.91 h50
  text "Top Overlay" at -444.79,6969.91 h50
  text "2" at -787.72,6869.91 h50
  text "Top Solder" at -444.79,6869.91 h50
  text "Solder Resist" at 331.33,6869.91 h50
  text "0.80mil" at 1049.14,6869.91 h50
  text "3.5" at 1592,6869.91 h50
  text "3" at -787.72,6769.91 h50
  text "TOP" at -444.79,6769.91 h50
  text "Copper" at 331.33,6769.91 h50
  text "1.60mil" at 1049.14,6769.91 h50
  text "5" at -940.77,6764.82 h60
  text "4" at -787.72,6669.91 h50
  text "Dielectric 1" at -444.79,6669.91 h50
  text "RO4835 LOPRO" at 331.33,6669.91 h50
  text "4.00mil" at 1049.14,6669.91 h50
  text "3.66" at 1592,6669.91 h50
  text "5" at -787.72,6569.91 h50
  text "L2" at -444.79,6569.91 h50
  text "Copper" at 331.33,6569.91 h50
  text "1.20mil" at 1049.14,6569.91 h50
  text "IMPEDANCE TABLE :" at 3600.83,6555.94 h70
  text "L1-L2" at -1106.13,6551.81 h60 r90
  text "5" at 3430.22,6544.62 h70
  text "6" at -787.72,6469.91 h50
  text "Dielectric2" at -444.79,6469.91 h50
  text "FR4 370HR" at 331.33,6469.91 h50
  text "2.85mil" at 1049.14,6469.91 h50
  text "3.9" at 1592,6469.91 h50
  text "7" at -787.72,6369.91 h50
  text "Dielectric 3" at -444.79,6369.91 h50
  text "FR4 370HR" at 331.33,6369.91 h50
  text "2.85mil" at 1049.14,6369.91 h50
  text "3.9" at 1592,6369.91 h50
  text "8" at -787.72,6269.91 h50
  text "L3" at -444.79,6269.91 h50
  text "Copper" at 331.33,6269.91 h50
  text "1.20mil" at 1049.14,6269.91 h50
  text "LAYER NO" at 3653.01,6214.39 h70
  text "CONDUCTOR WIDTH" at 4298.52,6214.39 h70
  text "IMPEDANCE +/-10%" at 6498.49,6214.26 h70
  text "REFERENCE GND" at 7679.53,6214.26 h70
  text "9" at -787.72,6169.91 h50
  text "Dielectric4" at -444.79,6169.91 h50
  text "FR4 370HR" at 331.33,6169.91 h50
  text "28.00mil" at 1049.14,6169.91 h50
  text "4.36" at 1592,6169.91 h50
  text "DIFF. / PAIR / SPACING" at 5360.47,6154.24 h70
  text "CPWG / SPACING" at 5898.82,6148.65 h70
  text "10" at -787.72,6069.91 h50
  text "L4" at -444.79,6069.91 h50
  text "Copper" at 331.33,6069.91 h50
  text "1.20mil" at 1049.14,6069.91 h50
  text "L1-L6" at -1287.73,6062.58 h60 r90
  text "11" at -787.72,5969.91 h50
  text "Dielectric5" at -444.79,5969.91 h50
  text "FR4 370HR" at 331.33,5969.91 h50
  text "2.92mil" at 1049.14,5969.91 h50
  text "3.9" at 1592,5969.91 h50
  text "7.08mil" at 4585.89,5945.53 h70
  text "1 (TOP)" at 3762.55,5943.06 h70
  text "GND" at 7928.75,5942.93 h70
  text "6.73mil" at 5934.76,5942.19 h70
  text "N/A" at 5444.9,5939.72 h70
  text "50ohm" at 6746,5939.67 h70
  text "12" at -787.72,5869.91 h50
  text "Dielectric 6" at -444.79,5869.91 h50
  text "FR4 370HR" at 331.33,5869.91 h50
  text "2.92mil" at 1049.14,5869.91 h50
  text "3.9" at 1592,5869.91 h50
  text "13" at -787.72,5769.91 h50
  text "L5" at -444.79,5769.91 h50
  text "Copper" at 331.33,5769.91 h50
  text "1.20mil" at 1049.14,5769.91 h50
  text "14" at -787.72,5669.91 h50
  text "Dielectric7" at -444.79,5669.91 h50
  text "FR4 370HR" at 331.33,5669.91 h50
  text "4.00mil" at 1049.14,5669.91 h50
  text "4.26" at 1592,5669.91 h50
  text "5.2mil" at 4585.89,5650.53 h70
  text "1 (TOP)" at 3762.55,5648.06 h70
  text "GND" at 7928.75,5647.93 h70
  text "5mil" at 5444.9,5644.72 h70
  text "N/A" at 5979.8,5644.59 h70
  text "100ohm" at 6746,5644.67 h70
  text "15" at -787.72,5569.91 h50
  text "BOTTOM" at -444.79,5569.91 h50
  text "Copper" at 331.33,5569.91 h50
  text "1.60mil" at 1049.14,5569.91 h50
  text "16" at -787.72,5469.91 h50
  text "Bottom Solder" at -444.79,5469.91 h50
  text "Solder Resist" at 331.33,5469.91 h50
  text "0.80mil" at 1049.14,5469.91 h50
  text "3.5" at 1592,5469.91 h50
  text "17" at -787.72,5369.91 h50
  text "Bottom Overlay" at -444.79,5369.91 h50
  text "THIS IS AN IMPEDANCE CONTROLLED BOARD." at -138.1,5200.05 h75
  text "NOTE :" at -1292.53,5078.05 h75
  text "EXTERNAL LAYER CU THICKNESSES ARE FINISHED THICKNESS AFTER PLATING." at -1218.64,4910.1 h75
M13 Component Bodies Top:
  text ".Layer_Name" at -523,-1458.49 h60
M14 Component Bodies Bottom:
  text ".Layer_Name" at -523,-1458.49 h60
M15 Courtyards Top:
  text ".Layer_Name" at -523,-1458.49 h60
M16 Courtyards Bottom:
  text ".Layer_Name" at -523,-1458.49 h60
Drill Drawing:
  circle w9: c3144.49,3818.01 r27.78
  lines w9: 3116.71,3040.24 3172.27,3040.24 3172.27,3095.79 3116.71,3095.79 3116.71,3040.24 ; 3116.71,3970.79 3172.27,3970.79 3144.49,3915.24 3116.71,3970.79
  lines w10: 3066.68,3002.74 10059.06,3002.74 ; 3066.68,4502.74 10059.06,4502.74 ; 3067.25,4804.65 9682.22,4804.65 ; 3067.25,4929.65 9682.22,4929.65 ; 3150.75,5076.27 3884.08,5076.27 ; 3527.88,2877.74 3527.88,4627.74 ; 3528.44,4679.65 3528.44,5054.65 ; 4029.08,2877.74 4029.08,4627.74 ; 4029.64,4679.65 4029.64,5054.65 ; 4889.06,4679.65 4889.06,5054.65 ; 4988.46,2877.74 4988.46,4627.74 ; 5312.76,4679.65 5312.76,5054.65 ; 5412.16,2877.74 5412.16,4627.74 ; 5926.39,4679.65 5926.39,5054.65 ; 6025.79,2877.74 6025.79,4627.74 ; 6649.99,4679.65 6649.99,5054.65 ; 6985.18,2877.74 6985.18,4627.74 ; 7783.46,4679.65 7783.46,5054.65 ; 8118.65,2877.74 8118.65,4627.74 ; 8776.97,4679.65 8776.97,5054.65 ; 9112.16,2877.74 9112.16,4627.74 ; 3066.68,2877.74 10059.06,2877.74 10059.06,4627.74 3066.68,4627.74 3066.68,2877.74 ; 3067.25,4679.65 9682.22,4679.65 9682.22,5054.65 3067.25,5054.65 3067.25,4679.65
  text "DRILL CHART :" at 3150.16,5099.49 h60
  text "Symbol" at 3142.25,4967.15 h60
  text "Count" at 3565.94,4967.15 h60
  text "Hole Size" at 4067.14,4967.15 h60
  text "Plated" at 4926.56,4967.15 h60
  text "Hole Type" at 5350.26,4967.15 h60
  text "Hole Length" at 5963.89,4967.15 h60
  text "Routed Path Length" at 6687.49,4967.15 h60
  text "Drill Layer Pair" at 7820.96,4967.15 h60
  text "Tolerance" at 8814.47,4967.15 h60
  text "508" at 3565.94,4842.15 h50
  text "5.90mil (0.150mm)" at 4067.14,4842.15 h50
  text "PTH" at 4926.56,4842.15 h50
  text "Round" at 5350.26,4842.15 h50
  text "-" at 5963.89,4842.15 h50
  text "-" at 6687.49,4842.15 h50
  text "TOP - L2" at 7820.96,4842.15 h50
  text "+0.00mil/-5.90mil" at 8814.47,4842.15 h50
  text "A" at 3117.55,4833.16 h55.56
  text "508 Total" at 3565.94,4717.15 h50
  text "Symbol" at 3141.68,4540.24 h60
  text "Count" at 3565.38,4540.24 h60
  text "Hole Size" at 4066.58,4540.24 h60
  text "Plated" at 5025.96,4540.24 h60
  text "Hole Type" at 5449.66,4540.24 h60
  text "Hole Length" at 6063.29,4540.24 h60
  text "Routed Path Length" at 7022.68,4540.24 h60
  text "Drill Layer Pair" at 8156.15,4540.24 h60
  text "Hole Tolerance" at 9149.66,4540.24 h60
  text "15" at 3565.38,4415.24 h50
  text "7.87mil (0.200mm)" at 4066.58,4415.24 h50
  text "PTH" at 5025.96,4415.24 h50
  text "Round" at 5449.66,4415.24 h50
  text "-" at 6063.29,4415.24 h50
  text "-" at 7022.68,4415.24 h50
  text "TOP - BOTTOM" at 8156.15,4415.24 h50
  text "+0.00mil/-7.87mil" at 9149.66,4415.24 h50
  text "B" at 3116.98,4406.24 h55.56
  text "621" at 3565.38,4290.24 h50
  text "12.20mil (0.310mm)" at 4066.58,4290.24 h50
  text "PTH" at 5025.96,4290.24 h50
  text "Round" at 5449.66,4290.24 h50
  text "-" at 6063.29,4290.24 h50
  text "-" at 7022.68,4290.24 h50
  text "TOP - BOTTOM" at 8156.15,4290.24 h50
  text "+0.00mil/-12.20mil" at 9149.66,4290.24 h50
  text "C" at 3116.98,4281.24 h55.56
  text "2" at 3565.38,4165.24 h50
  text "23.62mil (0.600mm)" at 4066.58,4165.24 h50
  text "PTH" at 5025.96,4165.24 h50
  text "Slot" at 5449.66,4165.24 h50
  text "51.18mil (1.300mm)" at 6063.29,4165.24 h50
  text "27.56mil (0.700mm)" at 7022.68,4165.24 h50
  text "TOP - BOTTOM" at 8156.15,4165.24 h50
  text "+/-3.00mil" at 9149.66,4165.24 h50
  text "D" at 3116.98,4156.24 h55.56
  text "2" at 3565.38,4040.24 h50
  text "33.47mil (0.850mm)" at 4066.58,4040.24 h50
  text "PTH" at 5025.96,4040.24 h50
  text "Round" at 5449.66,4040.24 h50
  text "-" at 6063.29,4040.24 h50
  text "-" at 7022.68,4040.24 h50
  text "TOP - BOTTOM" at 8156.15,4040.24 h50
  text "+/-3.00mil" at 9149.66,4040.24 h50
  text "E" at 3116.98,4031.24 h55.56
  text "2" at 3565.38,3915.24 h50
  text "39.37mil (1.000mm)" at 4066.58,3915.24 h50
  text "PTH" at 5025.96,3915.24 h50
  text "Slot" at 5449.66,3915.24 h50
  text "118.11mil (3.000mm)" at 6063.29,3915.24 h50
  text "78.74mil (2.000mm)" at 7022.68,3915.24 h50
  text "TOP - BOTTOM" at 8156.15,3915.24 h50
  text "+/-3.00mil" at 9149.66,3915.24 h50
  text "1" at 3565.38,3790.24 h50
  text "39.37mil (1.000mm)" at 4066.58,3790.24 h50
  text "PTH" at 5025.96,3790.24 h50
  text "Slot" at 5449.66,3790.24 h50
  text "137.80mil (3.500mm)" at 6063.29,3790.24 h50
  text "98.43mil (2.500mm)" at 7022.68,3790.24 h50
  text "TOP - BOTTOM" at 8156.15,3790.24 h50
  text "+/-3.00mil" at 9149.66,3790.24 h50
  text "8" at 3565.38,3665.24 h50
  text "40.00mil (1.016mm)" at 4066.58,3665.24 h50
  text "PTH" at 5025.96,3665.24 h50
  text "Round" at 5449.66,3665.24 h50
  text "-" at 6063.29,3665.24 h50
  text "-" at 7022.68,3665.24 h50
  text "TOP - BOTTOM" at 8156.15,3665.24 h50
  text "+/-3.00mil" at 9149.66,3665.24 h50
  text "H" at 3116.98,3656.24 h55.56
  text "2" at 3565.38,3540.24 h50
  text "40.16mil (1.020mm)" at 4066.58,3540.24 h50
  text "NPTH" at 5025.96,3540.24 h50
  text "Round" at 5449.66,3540.24 h50
  text "-" at 6063.29,3540.24 h50
  text "-" at 7022.68,3540.24 h50
  text "TOP - BOTTOM" at 8156.15,3540.24 h50
  text "+/-2.00mil" at 9149.66,3540.24 h50
  text "J" at 3116.98,3531.24 h55.56
  text "5" at 3565.38,3415.24 h50
  text "40.16mil (1.020mm)" at 4066.58,3415.24 h50
  text "PTH" at 5025.96,3415.24 h50
  text "Round" at 5449.66,3415.24 h50
  text "-" at 6063.29,3415.24 h50
  text "-" at 7022.68,3415.24 h50
  text "TOP - BOTTOM" at 8156.15,3415.24 h50
  text "+/-3.00mil" at 9149.66,3415.24 h50
  text "I" at 3126.24,3406.24 h55.56
  text "3" at 3565.38,3290.24 h50
  text "47.24mil (1.200mm)" at 4066.58,3290.24 h50
  text "PTH" at 5025.96,3290.24 h50
  text "Round" at 5449.66,3290.24 h50
  text "-" at 6063.29,3290.24 h50
  text "-" at 7022.68,3290.24 h50
  text "TOP - BOTTOM" at 8156.15,3290.24 h50
  text "+/-3.00mil" at 9149.66,3290.24 h50
  text "K" at 3116.98,3281.24 h55.56
  text "2" at 3565.38,3165.24 h50
  text "157.48mil (4.000mm)" at 4066.58,3165.24 h50
  text "PTH" at 5025.96,3165.24 h50
  text "Round" at 5449.66,3165.24 h50
  text "-" at 6063.29,3165.24 h50
  text "-" at 7022.68,3165.24 h50
  text "TOP - BOTTOM" at 8156.15,3165.24 h50
  text "+/-3.00mil" at 9149.66,3165.24 h50
  text "L" at 3116.98,3156.24 h55.56
  text "4" at 3565.38,3040.24 h50
  text "160.00mil (4.064mm)" at 4066.58,3040.24 h50
  text "NPTH" at 5025.96,3040.24 h50
  text "Round" at 5449.66,3040.24 h50
  text "-" at 6063.29,3040.24 h50
  text "-" at 7022.68,3040.24 h50
  text "TOP - BOTTOM" at 8156.15,3040.24 h50
  text "+/-2.00mil" at 9149.66,3040.24 h50
  text "667 Total" at 3565.38,2915.24 h50
  text "Slot definitions :" at 3141.68,2793.09 h50
  text "Routed Path Length" at 4004.12,2793.09 h50
  text "= Calculated from tool start centre position to tool end centre position." at 4924.88,2793.09 h50
  text "Hole Length" at 4004.12,2708.45 h50
  text "= Routed Path Length + Tool Size = Slot length as defined in the PCB layout" at 4583.32,2708.45 h50
  text "FAB" at -523,-1458.49 h60
M17 Embedded Cavity:
  text ".Layer_Name" at -523,-1458.49 h60
M18 Embedded Assembly:
  text ".Layer_Name" at -523,-1458.49 h60
M19 Embedded Keepout:
  text ".Layer_Name" at -523,-1458.49 h60

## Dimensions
0,0 to -32.75,-162.5 on M2 Board Dimensions
-32.75,2402.5 to 0,0 on M2 Board Dimensions
17.3,-16.34 to 200.82,-166.75 on M2 Board Dimensions
3068.39,2390.81 to 3173.4,2436.16 on M2 Board Dimensions
-102.75,-92.5 to 0,0 on M2 Board Dimensions
0,0 to 3077.25,-92.5 on M2 Board Dimensions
